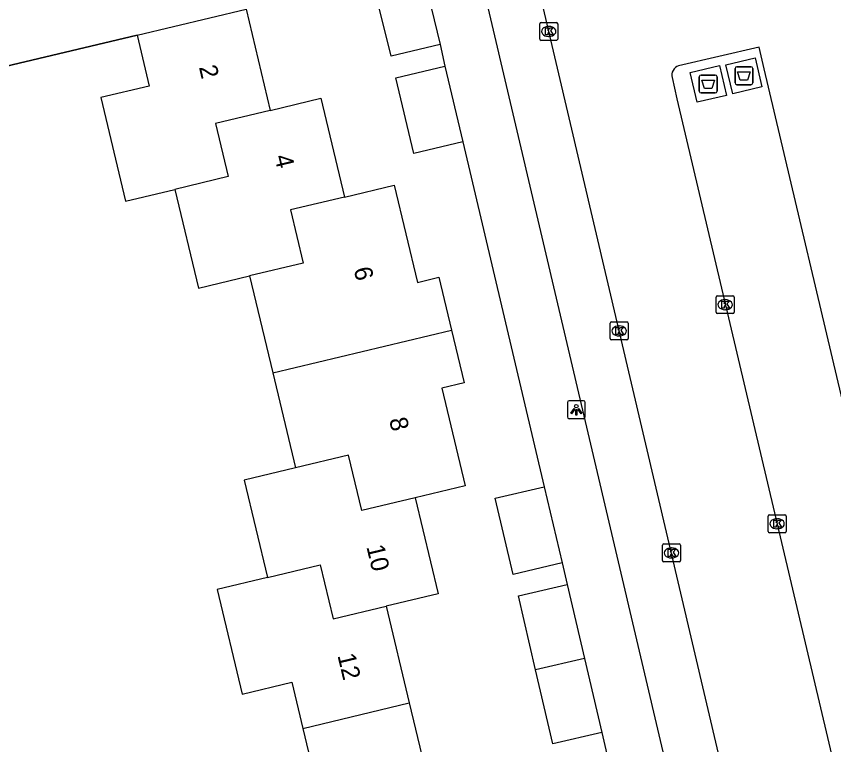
# Model space of a CAD drawing. Extents: x 158038 to 159242, y 380133 to 381214.
# Drawn here: x 158702.78 to 158748.37, y 380592.51 to 380633.11 of the extents above; entities that cross this region are included whole.
import ezdxf

# ---------------------------------------------------------------- set-up
doc = ezdxf.new("R2010")
doc.units = 0
for name, color, linetype in [('IMGEO_Afval_apart_plaats', 7, 'Continuous'), ('IMGEO_Fietspad_open', 7, 'Continuous'), ('IMGEO_Kolk', 7, 'Continuous'), ('IMGEO_Lichtpunt', 7, 'Continuous'), ('IMGEO_Muur', 7, 'Continuous'), ('IMGEO_Pand', 7, 'Continuous'), ('IMGEO_Pand_nummerreeks', 7, 'Continuous'), ('IMGEO_Rijbaan_lokaal_open', 7, 'Continuous'), ('IMGEO_Voetpad_gesloten', 7, 'Continuous'), ('IMGEO_Voetpad_open', 7, 'Continuous')]:
    doc.layers.add(name, color=color, linetype=linetype)

msp = doc.modelspace()

# ---------------------------------------------------------------- linework, layer by layer
at = {"layer": 'IMGEO_Afval_apart_plaats'}
for p, q in [((158742.969, 380630.302), (158743.759, 380630.302)), ((158743.759, 380630.302), (158742.969, 380630.302)), ((158740.977, 380629.842), (158741.767, 380629.842)), ((158741.767, 380629.842), (158740.977, 380629.842)), ((158742.869, 380629.402), (158742.869, 380630.202)), ((158742.869, 380630.202), (158742.869, 380629.402)), ((158743.859, 380630.202), (158743.859, 380629.402)), ((158743.859, 380629.402), (158743.859, 380630.202)), ((158740.877, 380628.942), (158740.877, 380629.742)), ((158740.877, 380629.742), (158740.877, 380628.942)), ((158741.867, 380629.742), (158741.867, 380628.942)), ((158741.867, 380628.942), (158741.867, 380629.742)), ((158743.759, 380629.302), (158742.969, 380629.302)), ((158742.969, 380629.302), (158743.759, 380629.302)), ((158741.767, 380628.842), (158740.977, 380628.842)), ((158740.977, 380628.842), (158741.767, 380628.842))]:
    msp.add_line(p, q, dxfattribs=at)
for points in [[(158743.012, 380630.016), (158743.716, 380630.016), (158743.567, 380629.546), (158743.161, 380629.546), (158743.012, 380630.016)], [(158741.02, 380629.556), (158741.724, 380629.556), (158741.575, 380629.086), (158741.169, 380629.086), (158741.02, 380629.556)]]:
    msp.add_lwpolyline(points, dxfattribs=at)
for centre, start, end in [((158742.969, 380630.202), 90, 180), ((158742.969, 380630.202), 90, 180), ((158743.759, 380630.202), 0, 90), ((158743.759, 380630.202), 360, 90), ((158740.977, 380629.742), 90, 180), ((158740.977, 380629.742), 90, 180), ((158741.767, 380629.742), 0, 90), ((158741.767, 380629.742), 360, 90), ((158742.969, 380629.402), 180, 270), ((158742.969, 380629.402), 180, 270), ((158743.759, 380629.402), 270, 0), ((158743.759, 380629.402), 270, 0), ((158740.977, 380628.942), 180, 270), ((158740.977, 380628.942), 180, 270), ((158741.767, 380628.942), 270, 0), ((158741.767, 380628.942), 270, 0)]:
    msp.add_arc(centre, 0.1, start, end, dxfattribs=at)
at = {"layer": 'IMGEO_Fietspad_open'}
msp.add_lwpolyline([(158727.607, 380639.865), (158741.77, 380579.626), (158742.026, 380578.534)], dxfattribs=at)
at = {"layer": 'IMGEO_Kolk'}
for p, q in [((158731.975, 380631.849), (158731.975, 380632.701)), ((158732.05, 380632.775), (158732.902, 380632.775)), ((158732.463, 380632.555), (158732.488, 380632.555)), ((158732.976, 380632.701), (158732.976, 380631.849)), ((158732.902, 380631.775), (158732.05, 380631.775)), ((158732.486, 380631.995), (158732.461, 380631.995)), ((158741.817, 380616.612), (158741.817, 380617.464)), ((158741.892, 380617.538), (158742.744, 380617.538)), ((158742.818, 380617.464), (158742.818, 380616.612)), ((158742.305, 380617.318), (158742.33, 380617.318)), ((158742.744, 380616.538), (158741.892, 380616.538)), ((158742.328, 380616.758), (158742.303, 380616.758)), ((158735.98, 380616.073), (158736.832, 380616.073)), ((158735.905, 380615.147), (158735.905, 380615.999)), ((158736.393, 380615.853), (158736.418, 380615.853)), ((158736.906, 380615.999), (158736.906, 380615.147)), ((158736.416, 380615.293), (158736.391, 380615.293)), ((158736.832, 380615.073), (158735.98, 380615.073)), ((158744.715, 380604.399), (158744.715, 380605.251)), ((158744.79, 380605.325), (158745.642, 380605.325)), ((158745.716, 380605.251), (158745.716, 380604.399)), ((158745.203, 380605.105), (158745.228, 380605.105)), ((158745.642, 380604.325), (158744.79, 380604.325)), ((158745.226, 380604.545), (158745.201, 380604.545)), ((158738.823, 380602.771), (158738.823, 380603.623)), ((158738.898, 380603.697), (158739.75, 380603.697)), ((158739.311, 380603.477), (158739.336, 380603.477)), ((158739.824, 380603.623), (158739.824, 380602.771)), ((158739.334, 380602.917), (158739.309, 380602.917)), ((158739.75, 380602.697), (158738.898, 380602.697))]:
    msp.add_line(p, q, dxfattribs=at)
for points in [[(158731.975, 380631.849), (158731.975, 380632.701)], [(158732.05, 380632.775), (158732.902, 380632.775)], [(158732.976, 380632.701), (158732.976, 380631.849)], [(158732.296, 380632.475), (158732.419, 380632.475), (158732.419, 380632.324), (158732.549, 380632.475), (158732.713, 380632.475), (158732.567, 380632.324), (158732.72, 380632.075), (158732.568, 380632.075), (158732.483, 380632.239), (158732.419, 380632.172), (158732.419, 380632.075), (158732.296, 380632.075), (158732.296, 380632.475)], [(158732.902, 380631.775), (158732.05, 380631.775)], [(158741.817, 380616.612), (158741.817, 380617.464)], [(158741.892, 380617.538), (158742.744, 380617.538)], [(158742.818, 380617.464), (158742.818, 380616.612)], [(158742.138, 380617.238), (158742.261, 380617.238), (158742.261, 380617.087), (158742.391, 380617.238), (158742.555, 380617.238), (158742.409, 380617.087), (158742.562, 380616.838), (158742.41, 380616.838), (158742.325, 380617.002), (158742.261, 380616.935), (158742.261, 380616.838), (158742.138, 380616.838), (158742.138, 380617.238)], [(158742.744, 380616.538), (158741.892, 380616.538)], [(158735.98, 380616.073), (158736.832, 380616.073)], [(158735.905, 380615.147), (158735.905, 380615.999)], [(158736.226, 380615.773), (158736.349, 380615.773), (158736.349, 380615.622), (158736.479, 380615.773), (158736.643, 380615.773), (158736.497, 380615.622), (158736.65, 380615.373), (158736.498, 380615.373), (158736.413, 380615.537), (158736.349, 380615.47), (158736.349, 380615.373), (158736.226, 380615.373), (158736.226, 380615.773)], [(158736.906, 380615.999), (158736.906, 380615.147)], [(158736.832, 380615.073), (158735.98, 380615.073)], [(158744.715, 380604.399), (158744.715, 380605.251)], [(158744.79, 380605.325), (158745.642, 380605.325)], [(158745.716, 380605.251), (158745.716, 380604.399)], [(158745.036, 380605.025), (158745.159, 380605.025), (158745.159, 380604.874), (158745.289, 380605.025), (158745.453, 380605.025), (158745.307, 380604.874), (158745.46, 380604.625), (158745.308, 380604.625), (158745.223, 380604.789), (158745.159, 380604.722), (158745.159, 380604.625), (158745.036, 380604.625), (158745.036, 380605.025)], [(158745.642, 380604.325), (158744.79, 380604.325)], [(158738.823, 380602.771), (158738.823, 380603.623)], [(158738.898, 380603.697), (158739.75, 380603.697)], [(158739.144, 380603.397), (158739.267, 380603.397), (158739.267, 380603.246), (158739.397, 380603.397), (158739.561, 380603.397), (158739.415, 380603.246), (158739.568, 380602.997), (158739.416, 380602.997), (158739.331, 380603.161), (158739.267, 380603.094), (158739.267, 380602.997), (158739.144, 380602.997), (158739.144, 380603.397)], [(158739.824, 380603.623), (158739.824, 380602.771)], [(158739.75, 380602.697), (158738.898, 380602.697)]]:
    msp.add_lwpolyline(points, dxfattribs=at)
for centre, start, end in [((158732.052, 380632.699), 91.552, 178.448), ((158732.052, 380632.699), 91.552, 178.448), ((158732.9, 380632.699), 1.552, 88.448), ((158732.9, 380632.699), 1.552, 88.448), ((158732.052, 380631.851), 181.552, 268.448), ((158732.052, 380631.851), 181.552, 268.448), ((158732.9, 380631.851), 271.552, 358.448), ((158732.9, 380631.851), 271.552, 358.448), ((158741.894, 380617.462), 91.552, 178.448), ((158741.894, 380617.462), 91.552, 178.448), ((158742.742, 380617.462), 1.552, 88.448), ((158742.742, 380617.462), 1.552, 88.448), ((158741.894, 380616.614), 181.552, 268.448), ((158741.894, 380616.614), 181.552, 268.448), ((158742.742, 380616.614), 271.552, 358.448), ((158742.742, 380616.614), 271.552, 358.448), ((158735.982, 380615.997), 91.552, 178.448), ((158735.982, 380615.997), 91.552, 178.448), ((158736.83, 380615.997), 1.552, 88.448), ((158736.83, 380615.997), 1.552, 88.448), ((158735.982, 380615.149), 181.552, 268.448), ((158735.982, 380615.149), 181.552, 268.448), ((158736.83, 380615.149), 271.552, 358.448), ((158736.83, 380615.149), 271.552, 358.448), ((158744.792, 380605.249), 91.552, 178.448), ((158744.792, 380605.249), 91.552, 178.448), ((158745.64, 380605.249), 1.552, 88.448), ((158745.64, 380605.249), 1.552, 88.448), ((158744.792, 380604.401), 181.552, 268.448), ((158744.792, 380604.401), 181.552, 268.448), ((158745.64, 380604.401), 271.552, 358.448), ((158745.64, 380604.401), 271.552, 358.448), ((158738.9, 380603.621), 91.552, 178.448), ((158738.9, 380603.621), 91.552, 178.448), ((158739.748, 380603.621), 1.552, 88.448), ((158739.748, 380603.621), 1.552, 88.448), ((158738.9, 380602.773), 181.552, 268.448), ((158738.9, 380602.773), 181.552, 268.448), ((158739.748, 380602.773), 271.552, 358.448), ((158739.748, 380602.773), 271.552, 358.448)]:
    msp.add_arc(centre, 0.0765, start, end, dxfattribs=at)
for centre, major_axis, ratio, start_param, end_param in [((158732.462, 380632.275), (-0.387, 0.002), 0.722429, 4.712389, 7.853982), ((158732.487, 380632.275), (-0.39, 0.002), 0.717154, 1.570796, 4.712389), ((158742.304, 380617.038), (-0.387, 0.002), 0.722429, 4.712389, 7.853982), ((158742.329, 380617.038), (-0.39, 0.002), 0.717154, 1.570796, 4.712389), ((158736.392, 380615.573), (-0.387, 0.002), 0.722429, 4.712389, 7.853982), ((158736.417, 380615.573), (-0.39, 0.002), 0.717154, 1.570796, 4.712389), ((158745.202, 380604.825), (-0.387, 0.002), 0.722429, 4.712389, 7.853982), ((158745.227, 380604.825), (-0.39, 0.002), 0.717154, 1.570796, 4.712389), ((158739.31, 380603.197), (-0.387, 0.002), 0.722429, 4.712389, 7.853982), ((158739.335, 380603.197), (-0.39, 0.002), 0.717154, 1.570796, 4.712389)]:
    msp.add_ellipse(centre, major_axis=major_axis, ratio=ratio, start_param=start_param, end_param=end_param, dxfattribs=at)
at = {"layer": 'IMGEO_Lichtpunt'}
for p, q in [((158733.516, 380611.583), (158733.516, 380610.776)), ((158733.516, 380611.583), (158733.516, 380610.776)), ((158734.418, 380611.678), (158733.61, 380611.678)), ((158734.418, 380611.678), (158733.61, 380611.678)), ((158734.512, 380610.776), (158734.512, 380611.583)), ((158734.512, 380610.776), (158734.512, 380611.583)), ((158733.61, 380610.682), (158734.418, 380610.682)), ((158733.61, 380610.682), (158734.418, 380610.682))]:
    msp.add_line(p, q, dxfattribs=at)
for points in [[(158733.89, 380611.247), (158733.929, 380611.219), (158733.741, 380610.957), (158733.703, 380610.984), (158733.89, 380611.247)], [(158733.992, 380611.199), (158734.039, 380611.199), (158734.039, 380610.877), (158733.992, 380610.877), (158733.992, 380611.199)], [(158734.102, 380611.219), (158734.14, 380611.246), (158734.327, 380610.984), (158734.288, 380610.956), (158734.102, 380611.219)]]:
    msp.add_lwpolyline(points, dxfattribs=at)
msp.add_circle((158734.015, 380611.381), 0.0994, dxfattribs=at)
for centre, start, end in [((158733.61, 380611.583), 90, 180), ((158733.61, 380611.583), 90, 180), ((158734.418, 380611.583), 0, 90), ((158734.418, 380611.583), 0, 90), ((158733.61, 380610.776), 180, 270), ((158733.61, 380610.776), 180, 270), ((158734.418, 380610.776), 270, 0), ((158734.418, 380610.776), 270, 360)]:
    msp.add_arc(centre, 0.0946, start, end, dxfattribs=at)
at = {"layer": 'IMGEO_Muur'}
msp.add_lwpolyline([(158709.509, 380632.073), (158689.357, 380627.287)], dxfattribs=at)
at = {"layer": 'IMGEO_Pand'}
for points in [[(158722.624, 380635.163), (158725.401, 380635.761), (158726.416, 380631.538)], [(158726.416, 380631.538), (158723.693, 380630.884), (158722.624, 380635.163)], [(158709.509, 380632.073), (158715.598, 380633.518)], [(158715.598, 380633.518), (158716.938, 380627.87)], [(158709.509, 380632.073), (158710.184, 380629.229), (158707.49, 380628.584), (158708.874, 380622.808), (158711.613, 380623.464)], [(158727.683, 380626.11), (158724.959, 380625.463), (158723.955, 380629.692), (158726.679, 380630.339)], [(158726.679, 380630.339), (158727.683, 380626.11)], [(158716.938, 380627.87), (158719.758, 380628.546), (158721.078, 380623.038)], [(158716.938, 380627.87), (158713.882, 380627.138), (158714.592, 380624.177), (158711.613, 380623.464)], [(158711.613, 380623.464), (158712.932, 380617.955), (158715.785, 380618.639)], [(158721.078, 380623.038), (158723.855, 380623.703), (158725.154, 380618.281), (158726.352, 380618.569), (158727.058, 380615.621)], [(158721.078, 380623.038), (158718.077, 380622.319), (158718.786, 380619.359), (158715.785, 380618.639)], [(158715.785, 380618.639), (158717.08, 380613.231)], [(158717.08, 380613.231), (158727.058, 380615.621)], [(158727.058, 380615.621), (158727.763, 380612.677), (158726.507, 380612.376), (158727.811, 380606.934), (158725.021, 380606.266)], [(158717.08, 380613.231), (158718.347, 380607.942)], [(158725.021, 380606.266), (158722.054, 380605.556), (158721.312, 380608.653), (158718.347, 380607.942)], [(158718.347, 380607.942), (158715.487, 380607.256), (158716.786, 380601.835)], [(158733.22, 380602.635), (158730.494, 380601.996), (158729.496, 380606.246), (158732.222, 380606.886)], [(158732.222, 380606.886), (158733.22, 380602.635)], [(158725.021, 380606.266), (158726.301, 380600.922), (158723.4, 380600.227)], [(158716.786, 380601.835), (158719.731, 380602.541), (158720.455, 380599.521), (158723.4, 380600.227)], [(158716.786, 380601.835), (158713.978, 380601.162), (158715.376, 380595.324), (158718.144, 380595.987), (158718.761, 380593.409)], [(158731.743, 380596.675), (158730.783, 380600.797), (158733.51, 380601.433)], [(158733.51, 380601.433), (158734.47, 380597.31)], [(158723.4, 380600.227), (158724.692, 380594.83)], [(158734.47, 380597.31), (158731.743, 380596.675)], [(158734.47, 380597.31), (158735.431, 380593.188)], [(158735.431, 380593.188), (158732.704, 380592.552), (158731.743, 380596.675)], [(158718.761, 380593.409), (158724.692, 380594.83)], [(158724.692, 380594.83), (158725.985, 380589.433)], [(158718.761, 380593.409), (158719.394, 380590.767), (158716.606, 380590.099), (158716.804, 380589.271), (158717.969, 380584.408), (158720.748, 380585.074)]]:
    msp.add_lwpolyline(points, dxfattribs=at)
at = {"layer": 'IMGEO_Rijbaan_lokaal_open'}
for points in [[(158744.707, 380580.31), (158730.863, 380639.184)], [(158754.353, 380588.474), (158744.502, 380630.188), (158744.215, 380631.389), (158739.723, 380630.346)], [(158739.369, 380629.697), (158739.628, 380628.513), (158749.349, 380587.303)]]:
    msp.add_lwpolyline(points, dxfattribs=at)
msp.add_arc((158739.865, 380629.848), 0.518, 105.8716, 196.9075, dxfattribs=at)
at = {"layer": 'IMGEO_Voetpad_gesloten'}
for points in [[(158742.739, 380628.802), (158742.358, 380630.416), (158743.99, 380630.801), (158744.371, 380629.187), (158742.739, 380628.802)], [(158740.748, 380628.321), (158740.359, 380629.98), (158741.996, 380630.364), (158742.385, 380628.705), (158740.748, 380628.321)]]:
    msp.add_lwpolyline(points, dxfattribs=at)
at = {"layer": 'IMGEO_Voetpad_open'}
for points in [[(158689.357, 380627.287), (158709.509, 380632.073)], [(158726.416, 380631.538), (158726.679, 380630.339)], [(158727.683, 380626.11), (158732.222, 380606.886)], [(158733.22, 380602.635), (158733.51, 380601.433)], [(158735.431, 380593.188), (158735.725, 380591.97)]]:
    msp.add_lwpolyline(points, dxfattribs=at)

# ---------------------------------------------------------------- texts
at = {"layer": 'IMGEO_Pand_nummerreeks'}
for s, rotation, p in [('2', 283.1401, (158712.959, 380630.287)), ('4', 283.4768, (158717.164, 380625.295)), ('6', 283.274, (158721.588, 380619.026)), ('8', 283.274, (158723.567, 380610.637)), ('10', 283.4698, (158722.3, 380603.541)), ('12', 283.4628, (158720.685, 380597.482))]:
    msp.add_text(s, height=1, rotation=rotation, dxfattribs=at).set_placement(p)

doc.saveas('drawing.dxf')
